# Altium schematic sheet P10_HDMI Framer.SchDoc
size 386 x 246 mm
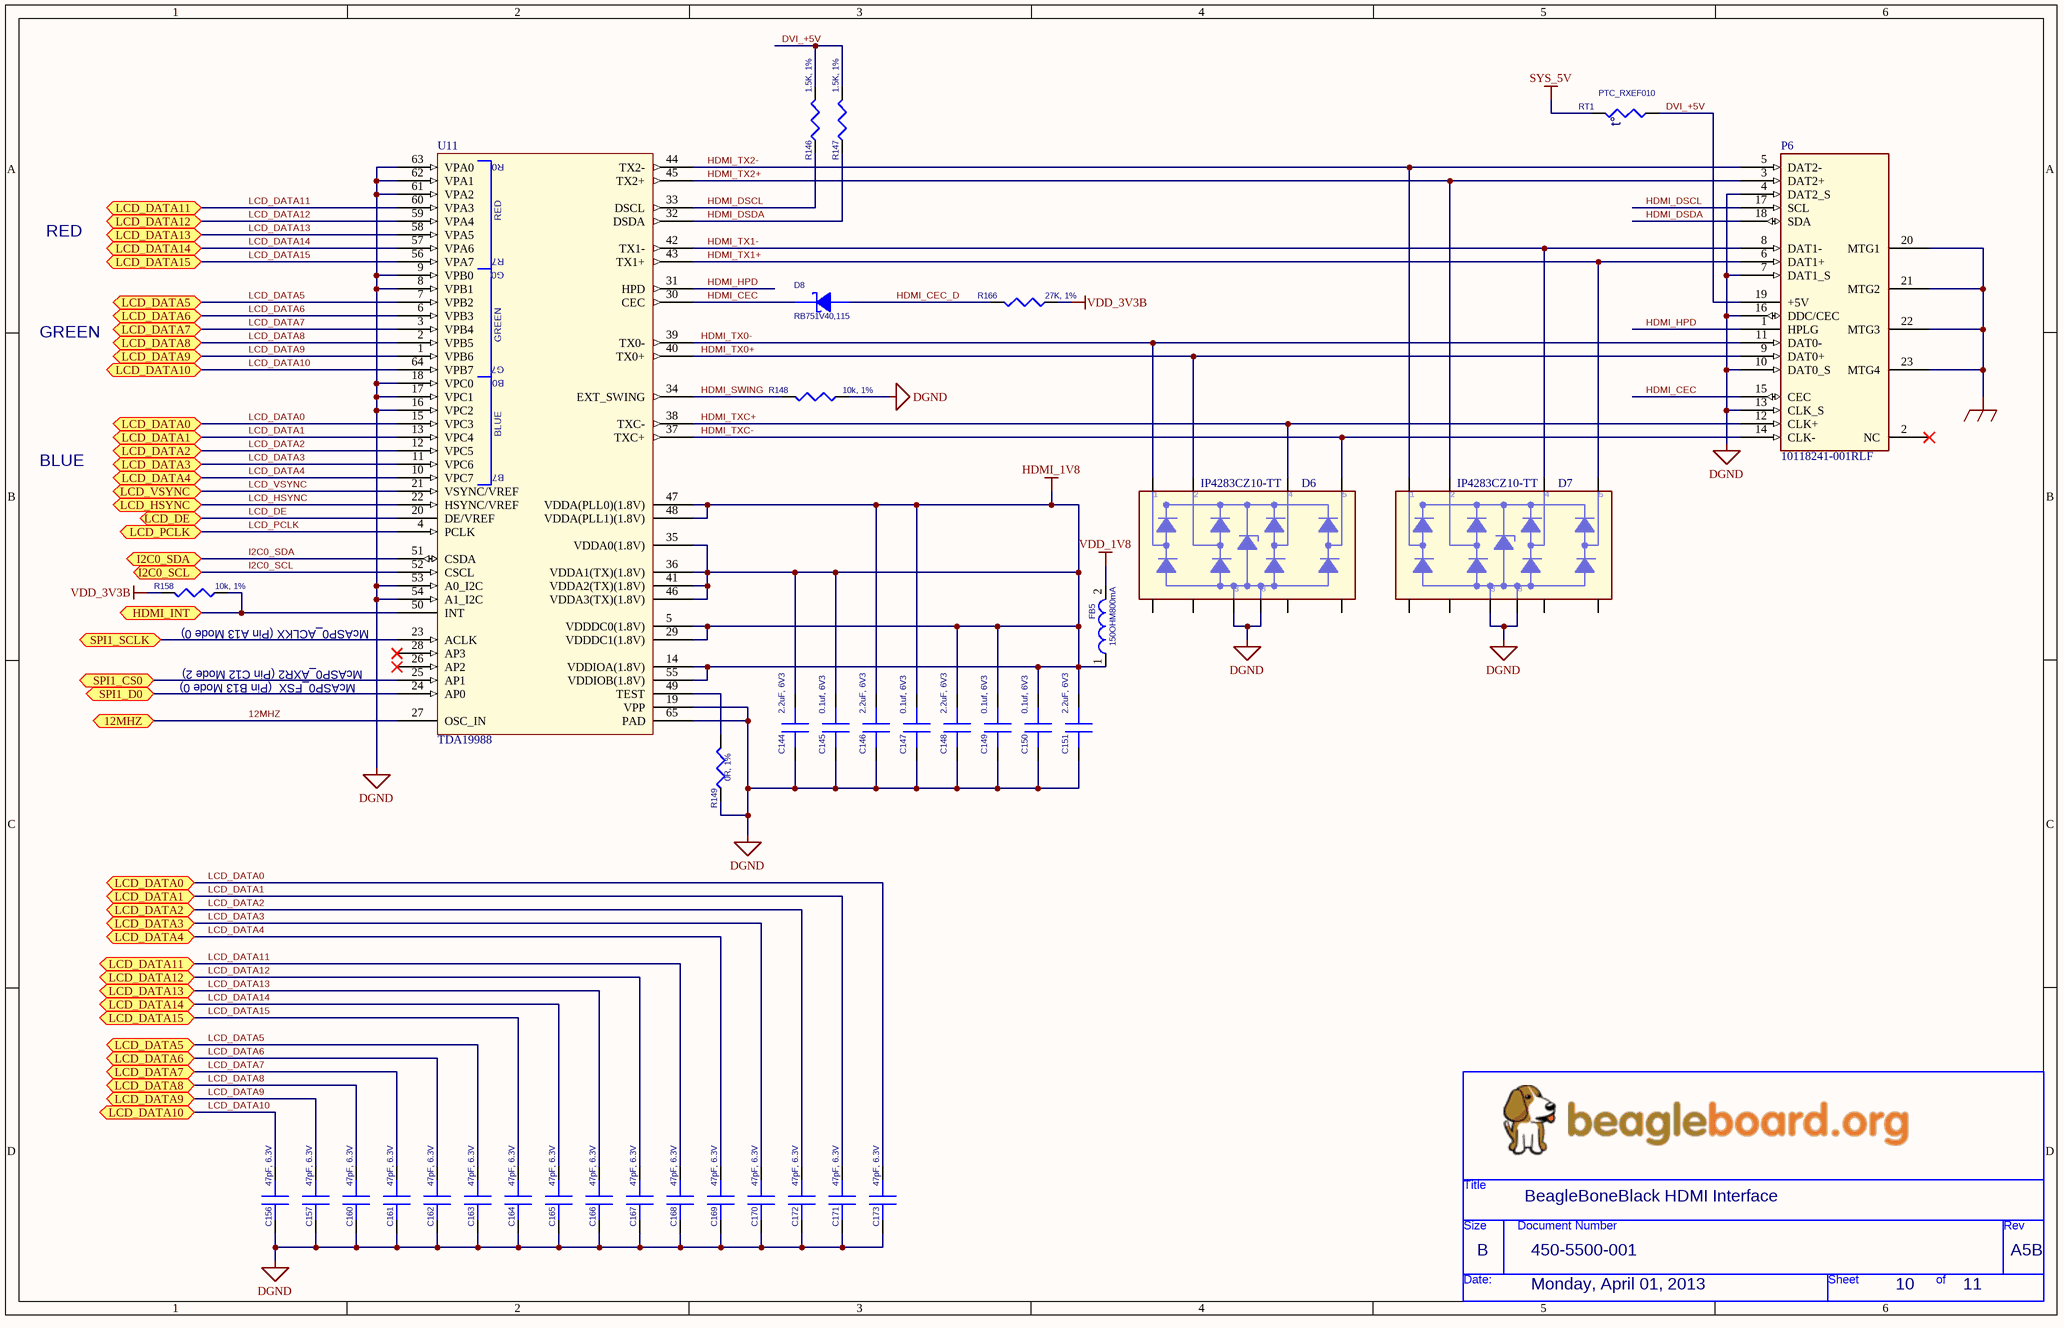
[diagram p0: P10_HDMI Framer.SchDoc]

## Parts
*  Page Create Date: Monday, April 01, 2013  Doc: 450-5500-001  RevCode: A5B  Title: BeagleBoneBlack HDMI Interface  Page Size: B  Page Number: 10  Page Count: 11  (hidden comment: BeagleBoard_org)  (graphical)
C144  2.2uF, 6V3  [402]
C145  0.1uf, 6V3  [402]
C146  2.2uF, 6V3  [402]
C147  0.1uf, 6V3  [402]
C148  2.2uF, 6V3  [402]
C149  0.1uf, 6V3  [402]
C150  0.1uf, 6V3  [402]
C151  2.2uF, 6V3  [402]
C156  47pF, 6.3V  [402]
C157  47pF, 6.3V  [402]
C160  47pF, 6.3V  [402]
C161  47pF, 6.3V  [402]
C162  47pF, 6.3V  [402]
C163  47pF, 6.3V  [402]
C164  47pF, 6.3V  [402]
C165  47pF, 6.3V  [402]
C166  47pF, 6.3V  [402]
C167  47pF, 6.3V  [402]
C168  47pF, 6.3V  [402]
C169  47pF, 6.3V  [402]
C170  47pF, 6.3V  [402]
C171  47pF, 6.3V  [402]
C172  47pF, 6.3V  [402]
C173  47pF, 6.3V  [402]
D6  IP4283CZ10-TT  [TSSOP10]
D7  IP4283CZ10-TT  [TSSOP10]
D8  RB751V40,115  [SOD323]
FB5  150OHM800mA  [SM-7351-IND-0805]
P6  10118241-001RLF  [CONN19_HDMI]
R146  1.5K, 1%  [402]
R147  1.5K, 1%  [402]
R148  10k, 1%  [402]
R149  0R, 1%  [402]
R158  10k, 1%  [402]
R166  27K, 1%  [402]
RT1  PTC_RXEF010  [POLYSW200-5638-310]
U11  TDA19988  [QFN64S9X9P5]

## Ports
12MHZ, HDMI_INT, I2C0_SCL, I2C0_SDA, LCD_DATA0, LCD_DATA1, LCD_DATA2, LCD_DATA3, LCD_DATA4, LCD_DATA5, LCD_DATA6, LCD_DATA7, LCD_DATA8, LCD_DATA9, LCD_DATA10, LCD_DATA11, LCD_DATA12, LCD_DATA13, LCD_DATA14, LCD_DATA15, LCD_DE, LCD_HSYNC, LCD_PCLK, LCD_VSYNC, SPI1_CS0, SPI1_D0, SPI1_SCLK

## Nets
DGND: C144.2 C145.2 C146.2 C147.2 C148.2 C149.2 C150.2 C151.2 C156.2 C157.2 C160.2 C161.2 C162.2 C163.2 C164.2 C165.2 C166.2 C167.2 C168.2 C169.2 C170.2 C171.2 C172.2 C173.2 D6.3 D6.8 D7.3 D7.8 P6.4(DAT2_S) P6.7(DAT1_S) P6.10(DAT0_S) P6.13(CLK_S) P6.16(DDC/CEC) R148.2(P2) R149.2(P2) U11.8(VPB1) U11.9(VPB0) U11.16(VPC2) U11.17(VPC1) U11.18(VPC0) U11.19(VPP) U11.53(A0_I2C) U11.54(A1_I2C) U11.61(VPA2) U11.62(VPA1) U11.63(VPA0) U11.65(PAD)
GND_EARTH: P6.20(MTG1) P6.21(MTG2) P6.22(MTG3) P6.23(MTG4)
HDMI_1V8: C144.1 C145.1 C146.1 C147.1 C148.1 C149.1 C150.1 C151.1 FB5.1 U11.5(VDDDC0(1.8V)) U11.14(VDDIOA(1.8V)) U11.29(VDDDC1(1.8V)) U11.35(VDDA0(1.8V)) U11.36(VDDA1(TX)(1.8V)) U11.41(VDDA2(TX)(1.8V)) U11.46(VDDA3(TX)(1.8V)) U11.47(VDDA(PLL0)(1.8V)) U11.48(VDDA(PLL1)(1.8V)) U11.55(VDDIOB(1.8V))
SYS_5V: RT1.1(P1)
VDD_1V8: FB5.2
VDD_3V3B: R158.1(P1) R166.2(P2)
12MHZ: U11.27(OSC_IN) ; port 12MHZ
DVI_+5V: P6.19(+5V) R146.1(P1) R147.1(P1) RT1.2(P2)
HDMI_CEC: D8.1(C) P6.15(CEC) U11.30(CEC)
HDMI_CEC_D: D8.2(A) R166.1(P1)
HDMI_DSCL: P6.17(SCL) R146.2(P2) U11.33(DSCL)
HDMI_DSDA: P6.18(SDA) R147.2(P2) U11.32(DSDA)
HDMI_HPD: P6.1(HPLG) U11.31(HPD)
HDMI_INT: R158.2(P2) U11.50(INT) ; port HDMI_INT
HDMI_SWING: R148.1(P1) U11.34(EXT_SWING)
HDMI_TX0+: D6.2 P6.9(DAT0+) U11.40(TX0+)
HDMI_TX0-: D6.1 P6.11(DAT0-) U11.39(TX0-)
HDMI_TX1+: D7.5 P6.6(DAT1+) U11.43(TX1+)
HDMI_TX1-: D7.4 P6.8(DAT1-) U11.42(TX1-)
HDMI_TX2+: D7.2 P6.3(DAT2+) U11.45(TX2+)
HDMI_TX2-: D7.1 P6.5(DAT2-) U11.44(TX2-)
HDMI_TXC+: D6.4 P6.12(CLK+) U11.38(TXC-)
HDMI_TXC-: D6.5 P6.14(CLK-) U11.37(TXC+)
I2C0_SCL: U11.52(CSCL) ; port I2C0_SCL
I2C0_SDA: U11.51(CSDA) ; port I2C0_SDA
LCD_DATA0: C173.1 U11.15(VPC3) ; port LCD_DATA0
LCD_DATA1: C171.1 U11.13(VPC4) ; port LCD_DATA1
LCD_DATA2: C172.1 U11.12(VPC5) ; port LCD_DATA2
LCD_DATA3: C170.1 U11.11(VPC6) ; port LCD_DATA3
LCD_DATA4: C169.1 U11.10(VPC7) ; port LCD_DATA4
LCD_DATA5: C163.1 U11.7(VPB2) ; port LCD_DATA5
LCD_DATA6: C162.1 U11.6(VPB3) ; port LCD_DATA6
LCD_DATA7: C161.1 U11.3(VPB4) ; port LCD_DATA7
LCD_DATA8: C160.1 U11.2(VPB5) ; port LCD_DATA8
LCD_DATA9: C157.1 U11.1(VPB6) ; port LCD_DATA9
LCD_DATA10: C156.1 U11.64(VPB7) ; port LCD_DATA10
LCD_DATA11: C168.1 U11.60(VPA3) ; port LCD_DATA11
LCD_DATA12: C167.1 U11.59(VPA4) ; port LCD_DATA12
LCD_DATA13: C166.1 U11.58(VPA5) ; port LCD_DATA13
LCD_DATA14: C165.1 U11.57(VPA6) ; port LCD_DATA14
LCD_DATA15: C164.1 U11.56(VPA7) ; port LCD_DATA15
LCD_DE: U11.20(DE/VREF) ; port LCD_DE
LCD_HSYNC: U11.22(HSYNC/VREF) ; port LCD_HSYNC
LCD_PCLK: U11.4(PCLK) ; port LCD_PCLK
LCD_VSYNC: U11.21(VSYNC/VREF) ; port LCD_VSYNC
SPI1_CS0: U11.25(AP1) ; port SPI1_CS0
SPI1_D0: U11.24(AP0) ; port SPI1_D0
SPI1_SCLK: U11.23(ACLK) ; port SPI1_SCLK
NetR149_1: R149.1(P1) U11.49(TEST)

Not connected (* = marked no-connect by the designer): D6 6 7 9 10; D7 6 7 9 10; P6 2(NC)*; U11 26(AP2)* 28(AP3)*

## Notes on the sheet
- RED
- GREEN
- BLUE
- McASP0_AXR2 (Pin C12 Mode 2)
- (near R158) McASP0_ACLKX (Pin A13 Mode 0)
- McASP0_FSX  (Pin B13 Mode 0)

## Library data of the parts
C144 C146 C148 C151 = CAP SMD: CAP CER 2.2UF 6.3V 10% X5R 0402; Manufacturer: TDK Corporation; Manufacturer Part Number: C1005X5R0J225K050BC; Capacitance: 2.2µF
C145 C147 C149 C150 = CAP SMD: CAP CER 0.1UF 6.3V 10% X5R 0402; Manufacturer: TDK Corporation; Manufacturer Part Number: C1005X5R0J104K050BA; Capacitance: 0.1µF
C156 C157 C160-C173 = CAP SMD: CAP CER 47PF 50V 5% NP0 0402; Manufacturer: TDK Corporation; Manufacturer Part Number: C1005C0G1H470J050BA; Temperature Coefficient: C0G, NP0
D6 D7 = 32CTQ030/TO_1: DIODE ESD PROT HDMI 10TSSOP; Manufacturer: NXP Semiconductors; Manufacturer Part Number: IP4283CZ10-TT,118; Voltage - Reverse Standoff (Typ): 3V; Voltage - Breakdown: 6V; Polarization: 4 Channel Array - Unidirectional
D8 = Zener: DIODE SCHOTTKY 40V 120MA SOD323; Manufacturer: NXP Semiconductors; Current - Average Rectified (Io): 120mA (DC); Voltage - Forward (Vf) (Max) @ If: 370mV @ 1mA; Speed: Small Signal =< 200mA (Io), Any Speed; Current - Reverse Leakage @ Vr: 500nA @ 30V; Capacitance @ Vr, F: 2pF @ 1V, 1MHz
FB5 = IND: FERRITE 800MA 150 OHM 0805 SMD; Manufacturer: Laird-Signal Integrity Products; Manufacturer Part Number: LI0805H151R-10; Impedance @ Frequency: 150 Ohm @ 100MHz; DC Resistance (DCR): 150 mOhm Max; Filter Type: Differential Mode - Single
P6 = Micro HDMI: CONN HDMI RECPT 19POS SMT R/A; Manufacturer: FCI; Number of Contacts: 19; Gender: Receptacle
R146 R147 = RES SMD: RES 1.50K OHM 1/16W 1% 0402 SMD; Manufacturer: Yageo; Manufacturer Part Number: RC0402FR-071K5L; Power (Watts): 0.063W, 1/16W; Temperature Coefficient: ±100ppm/°C
R148 R158 = RES SMD: RES 10K OHM 1/16W 5% 0402 SMD; Manufacturer: Rohm Semiconductor; Manufacturer Part Number: MCR01MZPJ103; Power (Watts): 0.063W, 1/16W; Temperature Coefficient: ±200ppm/°C
R149 = RES SMD: RES 0.0 OHM 1/16W 0402 SMD; Manufacturer: Yageo; Manufacturer Part Number: RC0402JR-070RL; Resistance (Ohms): 0.0; Power (Watts): 0.063W, 1/16W; Tolerance: Jumper
R166 = RES SMD: RES 27.0K OHM 1/16W 1% 0402 SMD; Manufacturer: Yageo; Manufacturer Part Number: RC0402FR-0727KL; Power (Watts): 0.063W, 1/16W; Temperature Coefficient: ±100ppm/°C
RT1 = PTC: POLYSWITCH PTC RESET 0.1A; Manufacturer: TE Connectivity; Current - Hold (Ih) (Max): 100mA; Current - Trip (It): 200mA; Current - Max: 40A; Voltage - Max: 60V; R Min/Max: 2.500 ~ 4.500 Ohm; Time to Trip: 4s
U11 = TDA19988: IC HDMI TRANSMITTER 64-HVQFN; Manufacturer: NXP Semiconductors; Manufacturer Part Number: TDA19988AHN/C1,551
